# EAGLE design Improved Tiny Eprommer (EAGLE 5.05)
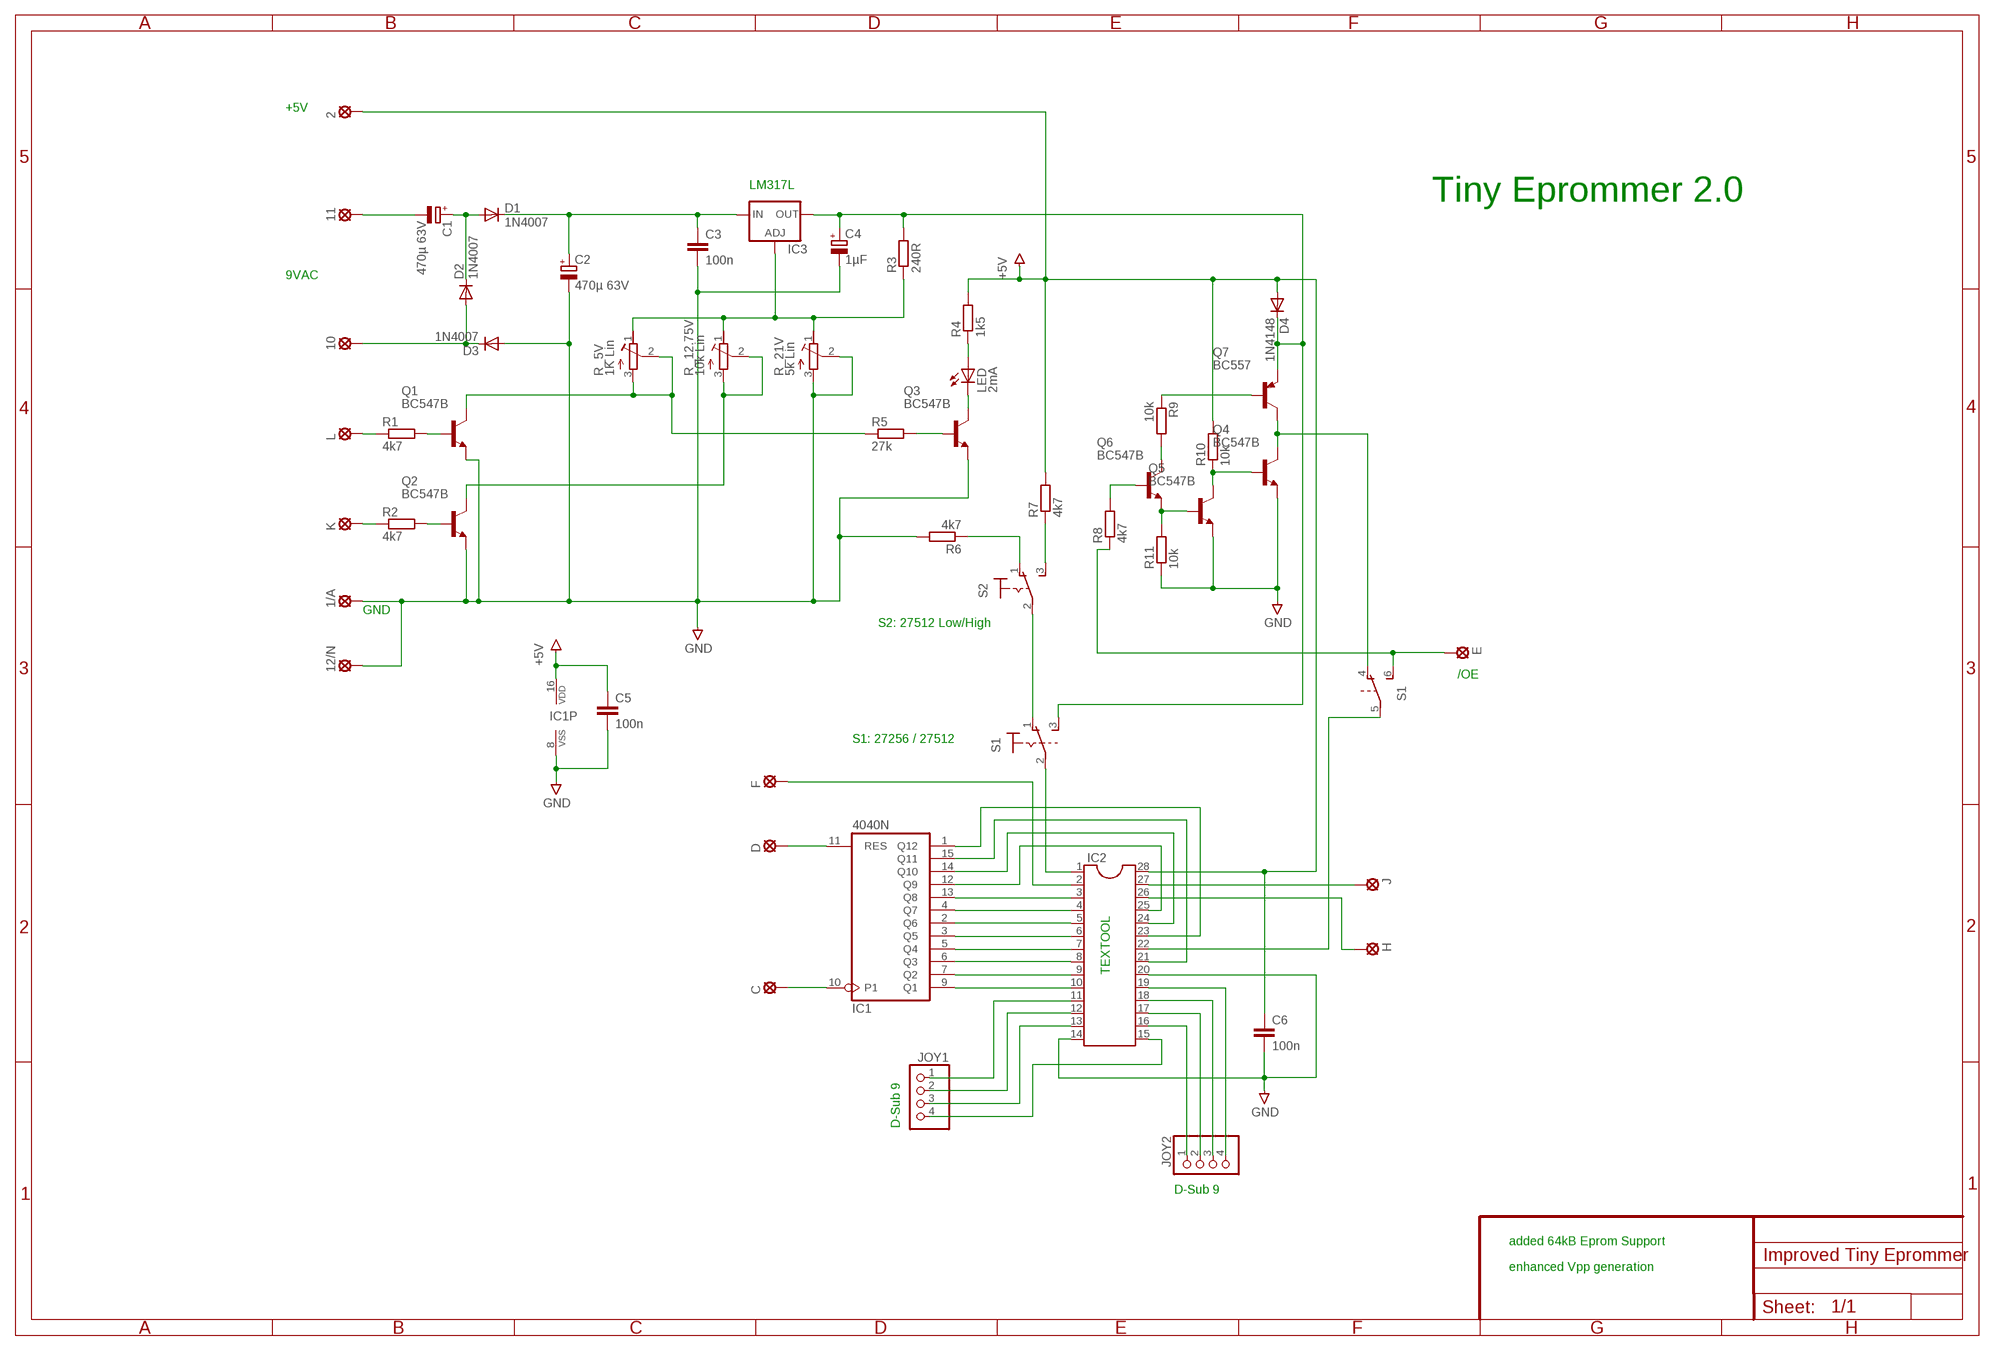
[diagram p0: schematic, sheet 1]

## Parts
1/A  LSP10  [LSP10]
2  LSP10  [LSP10]
10  LSP10  [LSP10]
11  LSP10  [LSP10]
12/N  LSP10  [LSP10]
C  LSP10  [LSP10]
C1  470µ 63V  CPOL-EUE5-13  [E5-13]
C2  470µ 63V  CPOL-EUE5-13  [E5-13]
C3  100n  C-EU050-025X075  [C050-025X075]
C4  1µF  CPOL-EUE5-6  [E5-6]
C5  100n  C-EU050-025X075  [C050-025X075]
C6  100n  C-EU050-025X075  [C050-025X075]
D  LSP10  [LSP10]
D1  1N4007  1N4004  [DO41-10]
D2  1N4007  1N4004  [DO41-10]
D3  1N4007  1N4004  [DO41-10]
D4  1N4148  [DO35-10]
E  LSP10  [LSP10]
F  LSP10  [LSP10]
H  LSP10  [LSP10]
IC1  4040N  [DIL16]
IC2  DIL28  [DIL28-6]
IC3  LM317L  [317L]
J  LSP10  [LSP10]
JOY1  PINHD-1X4  [1X04]
JOY2  PINHD-1X4  [1X04]
K  LSP10  [LSP10]
L  LSP10  [LSP10]
LED  2mA  LED3MM  [LED3MM]
Q1  BC547B  [TO92]
Q2  BC547B  [TO92]
Q3  BC547B  [TO92]
Q4  BC547B  [TO92]
Q5  BC547B  [TO92]
Q6  BC547B  [TO92]
Q7  BC557  [TO92]
R1  4k7  R-EU_0207/7  [0207/7]
R2  4k7  R-EU_0207/7  [0207/7]
R3  240R  R-EU_0207/7  [0207/7]
R4  1k5  R-EU_0207/12  [0207/12]
R5  27k  R-EU_0207/7  [0207/7]
R6  4k7  R-EU_0207/7  [0207/7]
R7  4k7  R-EU_0207/7  [0207/7]
R8  4k7  R-EU_0207/7  [0207/7]
R9  10k  R-EU_0207/7  [0207/7]
R10  10k  R-EU_0207/7  [0207/7]
R11  10k  R-EU_0207/7  [0207/7]
R_5V  1K Lin  R-TRIMMT18  [RTRIMT18]
R_12.75V  10k Lin  R-TRIMMT18  [RTRIMT18]
R_21V  5k Lin  R-TRIMMT18  [RTRIMT18]
S1  M9040P2  [M9040P2]
S2  M9040P  [M9040P]

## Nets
+5V: 2.MP C5.1 C6.1 D4.A IC1.16(VDD) IC2.28 R4.2 R7.2 R10.2
GND: 1/A.MP 12/N.MP C2.- C3.2 C4.- C5.2 C6.2 D3.A IC1.8(VSS) IC2.14 IC2.20 Q1.1(E) Q2.1(E) Q3.1(E) Q4.1(E) Q5.1(E) R6.2 R11.1 R_21V.2(S) R_21V.3(E)
N$1: IC2.22 S1.5(2:P)
N$2: IC2.1 S1.2(1:P)
N$3: S1.1(1:O) S2.2(P)
N$4: Q4.2(B) Q5.3(C) R10.1
N$5: 11.MP C1.-
N$6: C1.+ D1.A D2.C
N$7: 10.MP D2.A D3.C
N$9: C2.+ C3.1 D1.C IC3.3(IN)
N$10: R7.1 S2.3(S)
N$11: E.MP R8.1 S1.6(2:S)
N$12: IC3.1(ADJ) R3.1 R_5V.1(A) R_12.75V.1(A) R_21V.1(A)
N$13: LED.A R4.1
N$14: LED.K(C) Q3.3(C)
N$15: L.MP R1.1
N$16: Q1.2(B) R1.2
N$17: K.MP R2.1
N$18: Q2.2(B) R2.2
N$19: Q1.3(C) R5.1 R_5V.2(S) R_5V.3(E)
N$20: Q2.3(C) R_12.75V.2(S) R_12.75V.3(E)
N$21: IC1.9(Q1) IC2.10
N$22: Q3.2(B) R5.2
N$23: R6.1 S2.1(O)
N$24: C.MP IC1.10(P1)
N$25: D.MP IC1.11(RES)
N$26: IC1.7(Q2) IC2.9
N$27: IC1.6(Q3) IC2.8
N$28: IC1.5(Q4) IC2.7
N$29: IC1.3(Q5) IC2.6
N$30: IC1.2(Q6) IC2.5
N$31: IC1.4(Q7) IC2.4
N$32: IC1.13(Q8) IC2.3
N$33: IC1.12(Q9) IC2.25
N$34: IC1.14(Q10) IC2.24
N$35: IC1.15(Q11) IC2.21
N$36: IC1.1(Q12) IC2.23
N$37: F.MP IC2.2
N$38: IC2.27 J.MP
N$39: H.MP IC2.26
N$40: Q4.3(C) Q7.3(C) S1.4(2:O)
N$41: IC2.13 JOY1.3
N$42: IC2.12 JOY1.2
N$43: IC2.11 JOY1.1
N$44: IC2.15 JOY1.4
N$45: Q5.2(B) Q6.1(E) R11.2
N$46: IC2.16 JOY2.1
N$47: IC2.17 JOY2.2
N$48: IC2.18 JOY2.3
N$49: IC2.19 JOY2.4
N$50: Q6.3(C) R9.2
N$51: Q7.2(B) R9.1
N$52: Q6.2(B) R8.2
VPP: C4.+ D4.C IC3.2(OUT) Q7.1(E) R3.2 S1.3(1:S)

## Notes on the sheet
- +5V
- LM317L
- Tiny Eprommer 2.0
- 9VAC
- GND
- S2: 27512 Low/High
- /OE
- S1: 27256 / 27512
- TEXTOOL
- D-Sub 9
- D-Sub 9
- added 64kB Eprom Support
- enhanced Vpp generation

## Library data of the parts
1/A 2 10 11 12/N C D E F H J K L = solpad:LSP10: SOLDER PAD
C1 C2 C4 = rcl:CPOL-EU: POLARIZED CAPACITOR, European symbol
C3 C5 C6 = rcl:C-EU: CAPACITOR, European symbol
D1-D3 = diode:1N4004: DIODE
D4 = diode:1N4148: DIODE
IC1 = 40xx:4040: 12-stage binary/ripple COUNTER
IC2 = ic-package:DIL28: Dual In Line
IC3 = v-reg:LM317L: VOLTAGE REGULATOR
JOY1 JOY2 = pinhead:PINHD-1X4: PIN HEADER
LED = led:LED: LED
Q1-Q6 = transistor-npn:BC547*: NPN Transistor
Q7 = transistor-pnp:BC557: PNP Transistor
R1-R11 = rcl:R-EU_: RESISTOR, European symbol
R_5V R_12.75V R_21V = rcl:R-TRIMM: Trimm resistor
S1 = switch:M9040P2: TOGGLE SWITCH Marquardt
S2 = switch:M9040P: TOGGLE SWITCH Marquardt

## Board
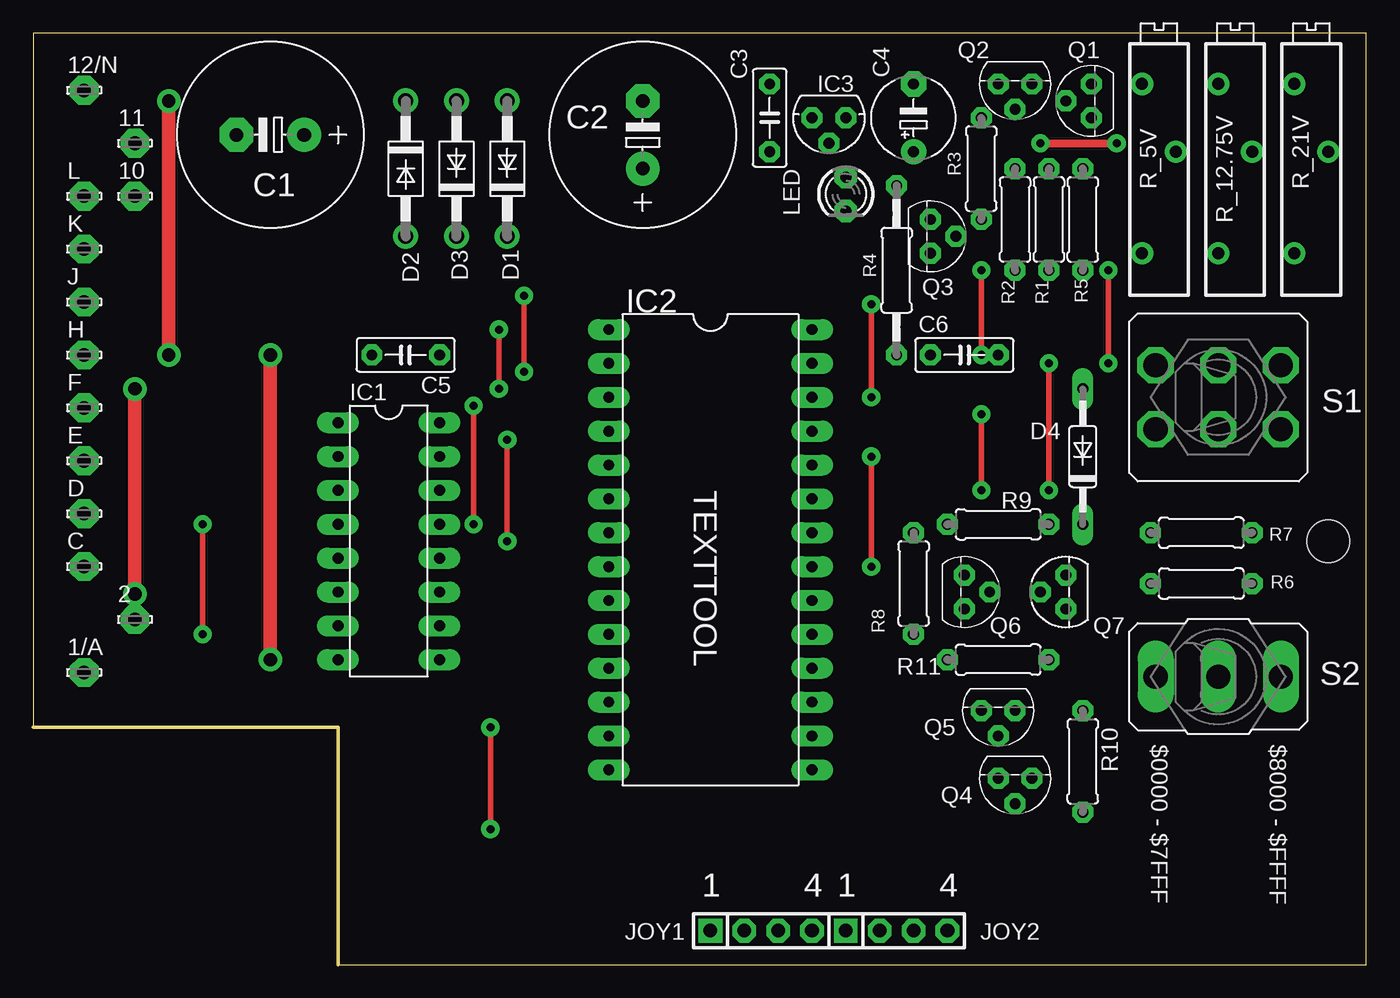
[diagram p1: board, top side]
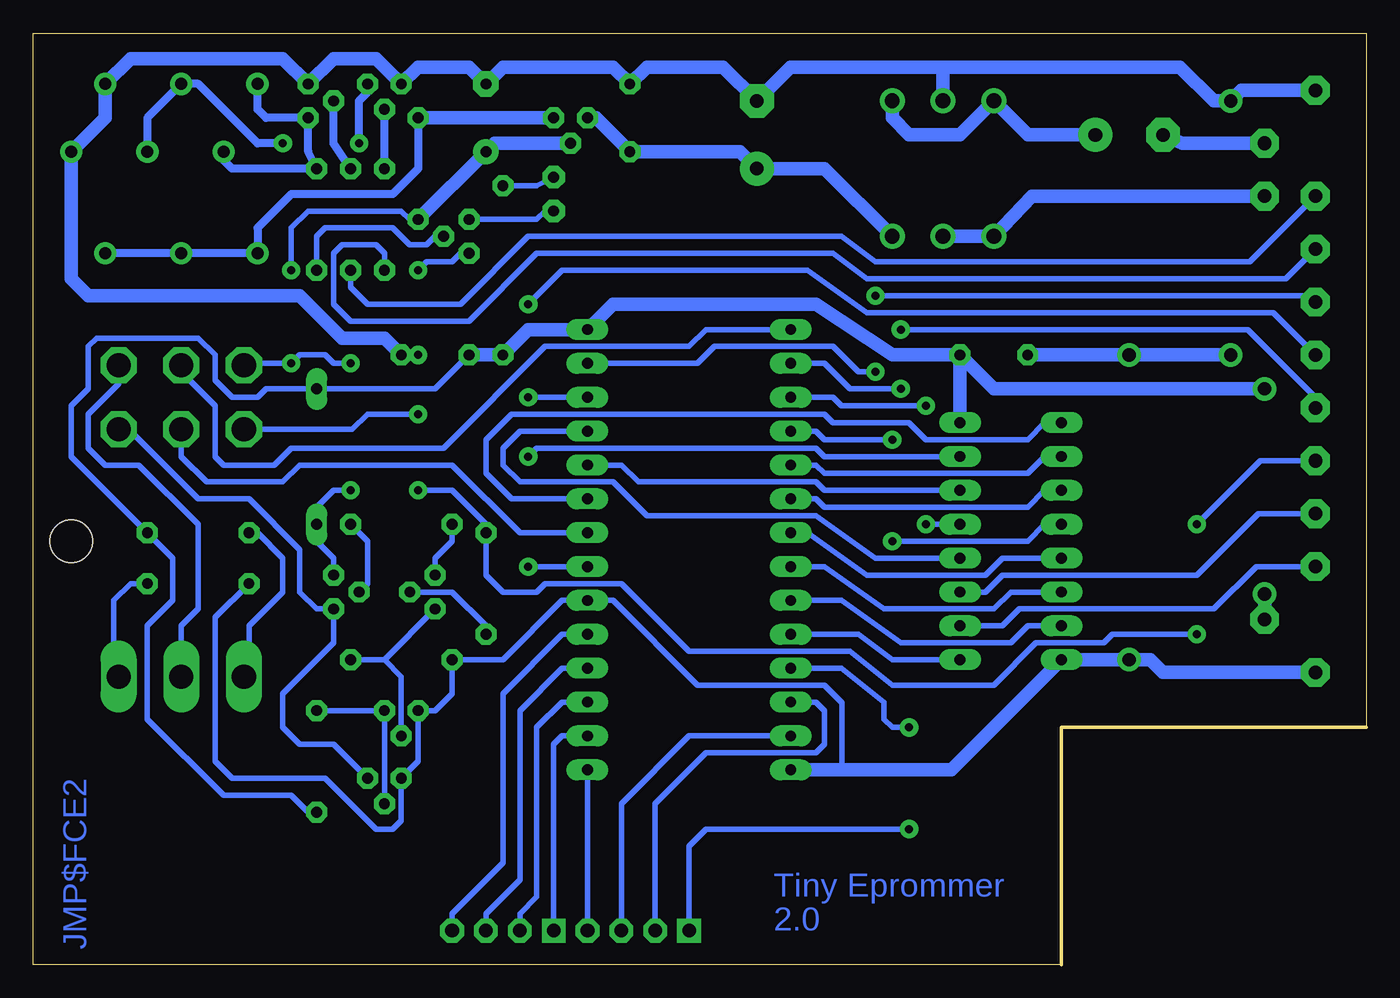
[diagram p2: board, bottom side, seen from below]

Size 100 x 69.84 mm. Coordinates in mm from the lower left corner, seen from the top.
Outline: 0,17.78 22.86,17.78 22.86,0 100,0 100,69.84 0,69.84 0,17.78
Copper layers (1*16): Top 0.035mm / dielectric 1.5mm / Bottom 0.035mm
Design rules "BWieck": minimum track width 12mil, minimum drill 24mil, track to track 12mil, track to pad 12mil, pad to pad 10mil, via to via 12mil, smd to smd 8mil, copper to edge 40mil, drill to drill 8mil, minimum pad ring 15mil, minimum via ring 15mil, stop-mask expansion 4mil, vias tented up to drill 0mil, thermal gap 10mil
Holes 3.2 mm at 97.16,31.75

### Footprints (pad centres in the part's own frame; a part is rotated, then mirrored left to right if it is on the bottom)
LSP10 = drill 1.016 pad 2.159 octagon: MP 0,0
E5-13 = drill 1.016 pad 2.54 round: + -2.54,0 | drill 1.016 pad 2.54 octagon: - 2.54,0
C050-025X075 = drill 0.813 octagon: 1 -2.54,0; 2 2.54,0
E5-6 = drill 0.813 pad 1.905 round: + -2.54,0 | drill 0.813 pad 1.905 octagon: - 2.54,0
DO41-10 = drill 1.118 round: A 5.08,0; C -5.08,0
DO35-10 = drill 0.813 long: A 5.08,0; C -5.08,0
DIL16 = drill 0.813 long: 1 -8.89,-3.81; 2 -6.35,-3.81; 3 -3.81,-3.81; 4 -1.27,-3.81; 5 1.27,-3.81; 6 3.81,-3.81; 7 6.35,-3.81; 8 8.89,-3.81; 9 8.89,3.81; 10 6.35,3.81; 11 3.81,3.81; 12 1.27,3.81; 13 -1.27,3.81; 14 -3.81,3.81; 15 -6.35,3.81; 16 -8.89,3.81
DIL28-6 = drill 0.813 long: 1 -16.51,-7.62; 2 -13.97,-7.62; 3 -11.43,-7.62; 4 -8.89,-7.62; 5 -6.35,-7.62; 6 -3.81,-7.62; 7 -1.27,-7.62; 8 1.27,-7.62; 9 3.81,-7.62; 10 6.35,-7.62; 11 8.89,-7.62; 12 11.43,-7.62; 13 13.97,-7.62; 14 16.51,-7.62; 15 16.51,7.62; 16 13.97,7.62; 17 11.43,7.62; 18 8.89,7.62; 19 6.35,7.62; 20 3.81,7.62; 21 1.27,7.62; 22 -1.27,7.62; 23 -3.81,7.62; 24 -6.35,7.62; 25 -8.89,7.62; 26 -11.43,7.62; 27 -13.97,7.62; 28 -16.51,7.62
317L = drill 0.813 octagon: 1 -1.27,0; 2 0,1.905; 3 1.27,0
1X04 = drill 1.016 square: 1 -3.81,0 | drill 1.016 octagon: 2 -1.27,0; 3 1.27,0; 4 3.81,0
LED3MM = drill 0.813 pad 1.676 octagon: A -1.27,0; K 1.27,0
TO92 = drill 0.813 octagon: 1 1.27,0; 2 0,1.905; 3 -1.27,0
0207/7 = drill 0.813 octagon: 1 -3.81,0; 2 3.81,0
0207/12 = drill 0.813 octagon: 1 -6.35,0; 2 6.35,0
RTRIMT18 = drill 0.9 round: 1 -7.62,1.27; 2 0,-1.27; 3 5.08,1.27
M9040P2 = drill 1.803 octagon: 1 -2.413,4.699; 2 -2.413,0; 3 -2.413,-4.699; 4 2.413,4.699; 5 2.413,0; 6 2.413,-4.699
M9040P = drill 1.803 long: 1 0,4.699; 2 0,0; 3 0,-4.699

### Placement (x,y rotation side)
1/A  3.81,21.91 0 top
2  7.62,25.88 0 top
10  7.62,57.63 0 top
11  7.62,61.59 0 top
12/N  3.81,65.56 0 top
C  3.81,29.84 0 top
C1  17.78,62.23 180 top
C2  45.72,62.23 90 top
C3  55.24,63.5 90 top
C4  66.04,63.5 90 top
C5  27.94,45.72 180 top
C6  69.85,45.72 0 top
D  3.81,33.81 0 top
D1  35.56,59.69 90 top
D2  27.94,59.69 270 top
D3  31.75,59.69 90 top
D4  78.74,38.1 90 top
E  3.81,37.78 0 top
F  3.81,41.75 0 top
H  3.81,45.72 0 top
IC1  26.67,31.75 270 top
IC2  50.8,31.11 270 top
IC3  59.69,63.5 180 top
J  3.81,49.69 0 top
JOY1  54.61,2.54 0 top
JOY2  64.77,2.54 0 top
K  3.81,53.66 0 top
L  3.81,57.63 0 top
LED  60.96,57.78 270 top
Q1  79.38,64.77 90 top
Q2  73.66,66.04 180 top
Q3  67.31,54.61 270 top
Q4  73.66,13.97 180 top
Q5  72.39,19.05 180 top
Q6  69.85,27.94 270 top
Q7  77.47,27.94 90 top
R1  76.2,55.88 90 top
R2  73.66,55.88 90 top
R3  71.12,59.69 270 top
R4  64.77,52.07 270 top
R5  78.74,55.88 270 top
R6  87.63,28.57 180 top
R7  87.63,32.38 0 top
R8  66.04,28.57 270 top
R9  72.39,33.02 180 top
R10  78.74,15.24 270 top
R11  72.39,22.86 0 top
R_5V  84.45,60.96 90 top
R_12.75V  90.17,60.96 90 top
R_21V  95.89,60.96 90 top
S1  88.9,42.55 270 top
S2  88.9,21.59 270 top

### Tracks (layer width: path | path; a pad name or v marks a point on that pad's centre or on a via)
+5V  (via drill 1)
  Top 1.016: v7.62,27.78 v7.62,43.18
  Bottom 0.406: C6.1 69.85,43.18 D4.A 82.55,43.18 83.19,42.55 85.09,42.55 86.36,43.81 86.36,45.72 87.63,46.99 95.25,46.99 95.89,46.35 95.89,43.18 97.16,41.91 97.16,38.1 R7.2 89.53,30.48 89.53,27.3 91.44,25.4 91.44,18.41 85.72,12.7 80.64,12.7 79.38,11.43 R10.2
  Bottom 1.016: v7.62,43.18 27.94,43.18 C5.1 | C5.1 35.56,45.72 41.27,49.53 56.52,49.53 IC2.28 62.87,47.62 R4.2 C6.1 | C5.1 IC1.16 | 2.MP v7.62,27.78
GND  (via drill 0.6, 1)
  Top 0.406: v71.12,45.72 v71.12,52.07
  Top 1.016: v17.78,22.86 v17.78,45.72 | v10.16,45.72 v10.16,64.77
  Bottom 0.406: Q3.1 67.94,53.34 68.58,52.7 70.48,52.7 v71.12,52.07 | C6.2 v71.12,45.72 | 39.32,14.61 39.32,19.64 40.64,20.95 50.16,20.95 56.52,27.3 IC2.20 60.33,27.3 64.77,22.86 R11.1 68.58,20.32 69.85,19.05 Q5.1 71.12,15.24 Q4.1 72.39,10.79 73.03,10.16 74.3,10.16 78.11,13.97 85.09,13.97 86.36,15.24 86.36,26.04 R6.2
  Bottom 1.016: 31.75,67.31 13.97,67.31 11.43,64.77 v10.16,64.77 9.37,65.56 12/N.MP | 31.75,67.31 43.18,67.31 C2.- 48.26,67.31 53.98,67.31 C3.2 56.52,67.31 64.77,67.31 C4.- 67.31,67.31 71.12,67.31 Q2.1 74.3,67.94 77.47,67.94 Q1.1 81.28,67.94 92.71,67.94 R_21V.3 94.61,63.5 R_21V.2 97.16,51.44 95.89,50.16 80.01,50.16 76.83,46.99 73.66,46.99 C6.2 | 1/A.MP 15.24,21.91 16.19,22.86 v17.78,22.86 IC1.8 31.11,14.61 39.32,14.61 IC2.14 | C5.2 v17.78,45.72 v10.16,45.72 | 31.75,67.31 D3.A
N$1
  Bottom 0.406: IC2.22 63.5,32.38 68.58,37.47 80.01,37.47 81.28,36.2 87,36.2 88.9,38.1 S1.5
N$2
  Bottom 0.406: S1.2 88.9,44.45 86.36,41.91 86.36,38.1 85.72,37.47 81.92,37.47 80.64,38.73 69.22,38.73 61.59,46.35 50.8,46.35 49.53,47.62 IC2.1
N$3
  Bottom 0.406: S1.1 93.6,43.56 95.89,41.27 95.89,38.73 94.61,37.47 92.08,37.47 87.63,33.02 87.63,26.67 88.9,25.4 S2.2
N$4
  Bottom 0.406: R10.1 Q5.3 Q4.2
N$5
  Bottom 1.016: 11.MP 13.81,61.59 C1.-
N$6
  Bottom 1.016: C1.+ 25.4,62.23 D2.C 30.48,62.23 34.29,62.23 35.56,63.5 D1.A
N$7
  Bottom 1.016: 10.MP 25.08,57.63 D2.A D3.C
N$9
  Bottom 1.016: IC3.3 57.78,63.5 C3.1 46.99,60.96 C2.+ 40.64,59.69 D1.C
N$10
  Bottom 0.406: R7.1 83.19,32.38 81.28,30.48 81.28,27.94 83.82,25.4 83.82,21.97 S2.3
N$11  (via drill 0.6)
  Top 0.406: v12.7,24.77 v12.7,33.02 | v71.12,35.56 v71.12,41.27
  Bottom 0.406: v12.7,24.77 19.05,24.77 19.68,24.13 24.77,24.13 27.94,20.95 35.56,20.95 38.73,23.5 50.8,23.5 55.88,28.57 61.59,28.57 62.23,27.94 64.77,27.94 66.04,29.21 R8.1 66.04,33.02 68.58,35.56 v71.12,35.56 | v12.7,33.02 7.94,37.78 E.MP | S1.6 76.07,40.13 74.93,41.27 v71.12,41.27
N$12
  Bottom 0.61: R3.1 71.12,59.69 73.03,57.78 80.64,57.78 83.19,55.24 R_5V.1 R_12.75V.1 R_21V.1
  Bottom 1.016: IC3.1 R3.1
N$13
  Bottom 0.406: LED.A 62.23,58.42 R4.1
N$14
  Bottom 0.406: LED.K 61.59,56.52 62.23,55.88 Q3.3
N$15
  Bottom 0.406: R1.1 76.2,50.8 74.93,49.53 67.94,49.53 62.87,54.61 39.37,54.61 36.83,52.7 8.73,52.7 L.MP
N$16
  Bottom 0.61: R1.2 77.47,61.59 Q1.2
N$17
  Bottom 0.406: R2.1 73.66,53.34 74.3,53.98 76.83,53.98 77.47,53.34 77.47,49.53 76.2,48.26 67.31,48.26 62.23,53.34 40.01,53.34 37.47,51.44 6.03,51.44 K.MP
N$18
  Bottom 0.61: R2.2 Q2.2
N$19
  Bottom 0.61: R_5V.3 83.19,64.14 82.55,63.5 Q1.3 79.38,60.96 R5.1 85.09,59.69 85.72,60.33 R_5V.2
N$20  (via drill 0.6)
  Top 0.61: v75.56,61.59 v81.28,61.59
  Bottom 0.61: Q2.3 74.93,65.41 75.56,64.77 v75.56,61.59 | v81.28,61.59 83.19,61.59 87.63,66.04 R_12.75V.3 91.44,63.5 R_12.75V.2
N$21
  Bottom 0.406: IC2.10 38.1,24.77 35.56,22.86 IC1.9
N$22
  Bottom 0.406: Q3.2 69.85,54.61 70.48,53.98 71.75,53.98 73.03,55.24 78.11,55.24 78.74,54.61 R5.2
N$23
  Bottom 0.406: R6.1 92.71,28.57 93.98,27.3 93.98,21.97 S2.1
N$24
  Bottom 0.406: IC1.10 27.3,25.4 26.04,26.67 11.43,26.67 8.26,29.84 C.MP
N$25
  Bottom 0.406: IC1.11 28.57,27.94 27.3,29.21 12.7,29.21 8.1,33.81 D.MP
N$26
  Bottom 0.406: IC1.7 25.4,25.4 26.67,24.13 34.92,24.13 39.37,27.3 IC2.9
N$27
  Bottom 0.406: IC1.6 26.67,27.94 27.94,26.67 36.2,26.67 40.64,29.84 IC2.8
N$28
  Bottom 0.406: IC1.5 27.3,30.48 28.57,29.21 37.47,29.21 41.91,32.38 IC2.7
N$29
  Bottom 0.406: IC1.3 24.13,35.56 25.4,34.29 40.64,34.29 41.27,34.92 IC2.6
N$30
  Bottom 0.406: IC1.2 24.13,38.1 25.4,36.83 40.64,36.83 41.27,37.47 IC2.5
N$31  (via drill 0.6)
  Top 0.406: v35.56,31.75 v35.56,39.37
  Bottom 0.406: IC1.4 24.13,33.02 25.4,31.75 v35.56,31.75 | IC2.4 41.27,40.01 40.64,39.37 v35.56,39.37
N$32  (via drill 0.6)
  Top 0.406: v33.02,33.02 v33.02,41.91
  Bottom 0.406: IC1.13 v33.02,33.02 | v33.02,41.91 39.37,41.91 40.01,42.55 IC2.3
N$33
  Bottom 0.406: IC2.25 63.5,40.01 64.77,38.73 64.77,37.47 63.5,36.2 56.52,36.2 53.98,33.66 41.27,33.66 36.83,30.48 IC1.12
N$34
  Bottom 0.406: IC1.14 40.64,35.56 41.27,36.2 54.61,36.2 55.88,37.47 IC2.24
N$35  (via drill 0.6)
  Top 0.406: v62.87,38.1 v62.87,29.84
  Bottom 0.406: v62.87,29.84 IC2.21 | IC1.15 40.64,38.1 41.27,38.73 62.23,38.73 v62.87,38.1
N$36
  Bottom 0.406: IC1.1 24.13,40.64 25.4,39.37 33.02,39.37 34.29,40.64 40.01,40.64 40.64,41.27 64.14,41.27 66.04,39.37 66.04,36.83 64.14,34.92 IC2.23
N$37  (via drill 0.6)
  Top 0.406: v34.92,47.62 v34.92,43.18
  Bottom 0.406: v34.92,47.62 8.89,47.62 3.81,42.55 F.MP | IC2.2 40.64,45.09 38.73,43.18 v34.92,43.18
N$38  (via drill 0.6)
  Top 0.406: v36.83,50.16 v36.83,44.45
  Bottom 0.406: v36.83,50.16 4.29,50.16 J.MP | IC2.27 50.16,45.09 48.9,46.35 40.01,46.35 38.1,44.45 v36.83,44.45
N$39  (via drill 0.6)
  Top 0.406: v62.87,49.53 v62.87,42.55
  Bottom 0.406: v62.87,49.53 60.33,52.07 41.91,52.07 37.47,48.9 6.99,48.9 H.MP | v62.87,42.55 IC2.26
N$40
  Bottom 0.406: S1.4 92.84,40.13 87.63,34.92 83.82,34.92 80.01,31.11 80.01,27.94 78.74,26.67 Q7.3 77.47,24.13 81.28,20.32 81.28,17.78 80.01,16.51 77.47,16.51 Q4.3
N$41
  Bottom 0.406: JOY1.3 55.88,12.06 50.8,17.14 IC2.13
N$42
  Bottom 0.406: JOY1.2 53.34,12.06 49.53,15.88 41.27,15.88 40.64,16.51 40.64,19.05 41.27,19.68 IC2.12
N$43  (via drill 0.6)
  Top 0.406: v34.29,10.16 v34.29,17.78
  Bottom 0.406: JOY1.1 50.8,8.89 49.53,10.16 v34.29,10.16 | IC2.11 39.37,22.23 36.2,19.68 36.2,18.41 35.56,17.78 v34.29,17.78
N$44
  Bottom 0.406: JOY1.4 IC2.15
N$45
  Bottom 0.406: 73.66,22.86 R11.2 | 73.66,22.86 72.39,21.59 Q5.2 | 73.66,22.86 Q6.1
N$46
  Bottom 0.406: IC2.16 60.33,17.14 60.96,16.51 JOY2.1
N$47
  Bottom 0.406: JOY2.2 63.5,3.81 62.23,5.08 62.23,17.78 60.33,19.68 IC2.17
N$48
  Bottom 0.406: JOY2.3 66.04,3.81 63.5,6.35 63.5,19.05 60.33,22.23 IC2.18
N$49
  Bottom 0.406: JOY2.4 68.58,3.81 64.77,7.62 64.77,20.32 60.33,24.77 IC2.19
N$50
  Bottom 0.406: R9.2 68.58,31.75 69.85,30.48 Q6.3
N$51
  Bottom 0.406: R9.1 74.93,31.75 74.93,28.57 Q7.2
N$52
  Bottom 0.406: Q6.2 68.58,27.94 66.04,25.4 R8.2
VPP  (via drill 0.6)
  Top 0.406: v80.64,45.09 v80.64,52.07 | v76.2,35.56 v76.2,45.09
  Bottom 0.406: R3.2 71.75,55.88 72.39,56.52 79.38,56.52 80.64,55.24 v80.64,52.07 | S1.3 84.07,45.09 v80.64,45.09 80.01,45.72 78.11,45.72 77.47,45.09 v76.2,45.09 | Q7.1 77.47,30.48 78.74,31.75 D4.C 78.74,34.29 77.47,35.56 v76.2,35.56
  Bottom 1.016: IC3.2 65.41,61.59 C4.+ R3.2

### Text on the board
Bottom: JMP$FCE2 | Tiny Eprommer | 2.0
tPlace: TEXTTOOL | $0000 - $7FFF | $8000 - $FFFF | 1 | 4 | 1 | 4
